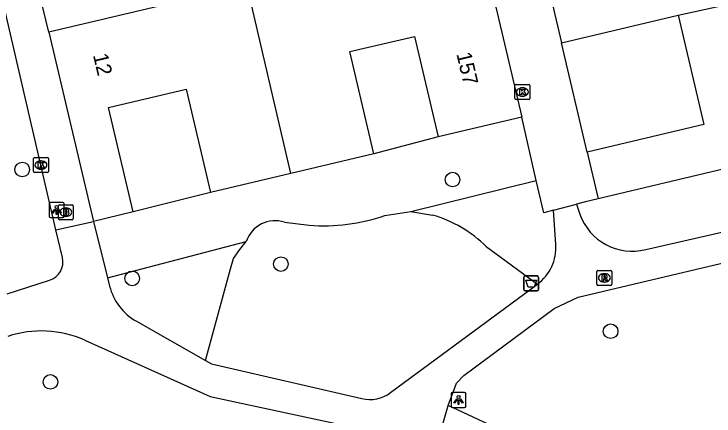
# Model space of a CAD drawing. Extents: x 162990 to 165007, y 383433 to 384336.
# Drawn here: x 164065.4 to 164112.18, y 383958.55 to 383985.38 of the extents above; entities that cross this region are included whole.
import ezdxf

# ---------------------------------------------------------------- set-up
doc = ezdxf.new("R2010")
doc.units = 0
for name, color, linetype in [('IMGEO_Afvalbak', 7, 'Continuous'), ('IMGEO_Boom', 7, 'Continuous'), ('IMGEO_Brandkraan', 7, 'Continuous'), ('IMGEO_Groenvoorziening', 7, 'Continuous'), ('IMGEO_Kolk', 7, 'Continuous'), ('IMGEO_Lichtpunt', 7, 'Continuous'), ('IMGEO_Pand', 7, 'Continuous'), ('IMGEO_Pand_nummerreeks', 7, 'Continuous'), ('IMGEO_Rioolput', 7, 'Continuous'), ('IMGEO_Voetpad_halfverhard', 7, 'Continuous'), ('IMGEO_Voetpad_open', 7, 'Continuous')]:
    doc.layers.add(name, color=color, linetype=linetype)

msp = doc.modelspace()

# ---------------------------------------------------------------- linework, layer by layer
at = {"layer": 'IMGEO_Afvalbak'}
for p, q in [((164099.571, 383967.895), (164100.361, 383967.895)), ((164100.361, 383967.895), (164099.571, 383967.895)), ((164099.471, 383966.995), (164099.471, 383967.795)), ((164099.471, 383967.795), (164099.471, 383966.995)), ((164100.461, 383967.795), (164100.461, 383966.995)), ((164100.461, 383966.995), (164100.461, 383967.795)), ((164100.361, 383966.895), (164099.571, 383966.895)), ((164099.571, 383966.895), (164100.361, 383966.895))]:
    msp.add_line(p, q, dxfattribs=at)
msp.add_lwpolyline([(164099.614, 383967.609), (164100.318, 383967.609), (164100.169, 383967.139), (164099.763, 383967.139), (164099.614, 383967.609)], dxfattribs=at)
for centre, start, end in [((164099.571, 383967.795), 90, 180), ((164099.571, 383967.795), 90, 180), ((164100.361, 383967.795), 0, 90), ((164100.361, 383967.795), 360, 90), ((164099.571, 383966.995), 180, 270), ((164099.571, 383966.995), 180, 270), ((164100.361, 383966.995), 270, 0), ((164100.361, 383966.995), 270, 0)]:
    msp.add_arc(centre, 0.1, start, end, dxfattribs=at)
at = {"layer": 'IMGEO_Boom'}
for centre in [(164065.947, 383975), (164094.708, 383974.328), (164083.237, 383968.686), (164073.296, 383967.732), (164105.273, 383964.207), (164067.835, 383960.826)]:
    msp.add_circle(centre, 0.489, dxfattribs=at)
at = {"layer": 'IMGEO_Brandkraan'}
for p, q in [((164068.361, 383971.725), (164068.361, 383972.577)), ((164068.436, 383972.651), (164069.288, 383972.651)), ((164069.362, 383972.577), (164069.362, 383971.725)), ((164068.849, 383972.431), (164068.874, 383972.431)), ((164069.288, 383971.651), (164068.436, 383971.651)), ((164068.872, 383971.871), (164068.847, 383971.871))]:
    msp.add_line(p, q, dxfattribs=at)
for points in [[(164068.361, 383971.725), (164068.361, 383972.577)], [(164068.436, 383972.651), (164069.288, 383972.651)], [(164069.362, 383972.577), (164069.362, 383971.725)], [(164068.709, 383972.351), (164068.709, 383971.951), (164068.922, 383971.951)], [(164068.94, 383972.351), (164068.709, 383972.351)], [(164068.888, 383972.27), (164068.834, 383972.27), (164068.834, 383972.194)], [(164068.834, 383972.194), (164068.887, 383972.194)], [(164068.896, 383972.118), (164068.834, 383972.118), (164068.834, 383972.037)], [(164069.288, 383971.651), (164068.436, 383971.651)], [(164068.834, 383972.037), (164068.896, 383972.037)]]:
    msp.add_lwpolyline(points, dxfattribs=at)
for centre, radius, start, end in [((164068.438, 383972.575), 0.0765, 91.552, 178.448), ((164068.438, 383972.575), 0.0765, 91.552, 178.448), ((164069.286, 383972.575), 0.0765, 1.552, 88.448), ((164069.286, 383972.575), 0.0765, 1.552, 88.448), ((164068.889, 383972.232), 0.0379, 267.8285, 90.9355), ((164068.897, 383972.077), 0.0404, 269.8759, 90.5077), ((164068.944, 383972.206), 0.145, 59.4692, 91.5367), ((164068.969, 383972.253), 0.0922, 285.5137, 58.1501), ((164068.974, 383972.061), 0.105, 301.3115, 78.989), ((164068.438, 383971.727), 0.0765, 181.552, 268.448), ((164068.438, 383971.727), 0.0765, 181.552, 268.448), ((164068.928, 383972.202), 0.251, 268.6676, 293.5347), ((164069.286, 383971.727), 0.0765, 271.552, 358.448), ((164069.286, 383971.727), 0.0765, 271.552, 358.448)]:
    msp.add_arc(centre, radius, start, end, dxfattribs=at)
for centre, major_axis, ratio, start_param, end_param in [((164068.848, 383972.151), (-0.387, 0.002), 0.722429, 4.712389, 7.853982), ((164068.873, 383972.151), (-0.39, 0.002), 0.717154, 1.570796, 4.712389)]:
    msp.add_ellipse(centre, major_axis=major_axis, ratio=ratio, start_param=start_param, end_param=end_param, dxfattribs=at)
at = {"layer": 'IMGEO_Groenvoorziening'}
for points in [[(164093.738, 383977.172), (164089.454, 383976.051)], [(164091.918, 383972.201), (164100.303, 383974.268)], [(164078.53, 383973.473), (164073.354, 383972.164)], [(164090.173, 383971.92), (164091.918, 383972.201)], [(164091.918, 383972.201), (164093.376, 383971.951)], [(164083.486, 383971.482), (164085.132, 383971.274)], [(164071.651, 383967.76), (164080.918, 383970.191)], [(164078.192, 383962.253), (164079.862, 383968.373), (164080.075, 383969.069), (164080.492, 383969.666), (164080.918, 383970.191)], [(164096.965, 383969.857), (164100.386, 383967.354)], [(164124.472, 383958.604), (164114.758, 383957.879), (164107.853, 383957.563), (164102.633, 383956.731), (164101.117, 383956.676), (164100.331, 383956.769), (164098.81, 383957.196), (164094.409, 383959.248)]]:
    msp.add_lwpolyline(points, dxfattribs=at)
for centre, radius, start, end in [((164082.856, 383969.536), 2.046, 72.0612, 161.3185), ((164086.081, 383983.861), 12.623, 265.6888, 288.9164), ((164091.028, 383963.804), 8.478, 45.5534, 73.9238)]:
    msp.add_arc(centre, radius, start, end, dxfattribs=at)
at = {"layer": 'IMGEO_Kolk'}
for p, q in [((164098.876, 383979.746), (164098.876, 383980.598)), ((164098.951, 383980.672), (164099.803, 383980.672)), ((164099.877, 383980.598), (164099.877, 383979.746)), ((164099.364, 383980.452), (164099.389, 383980.452)), ((164099.803, 383979.672), (164098.951, 383979.672)), ((164099.387, 383979.892), (164099.362, 383979.892)), ((164066.77, 383975.797), (164067.622, 383975.797)), ((164066.695, 383974.871), (164066.695, 383975.723)), ((164067.183, 383975.577), (164067.208, 383975.577)), ((164067.696, 383975.723), (164067.696, 383974.871)), ((164067.206, 383975.017), (164067.181, 383975.017)), ((164067.622, 383974.797), (164066.77, 383974.797))]:
    msp.add_line(p, q, dxfattribs=at)
for points in [[(164098.876, 383979.746), (164098.876, 383980.598)], [(164098.951, 383980.672), (164099.803, 383980.672)], [(164099.877, 383980.598), (164099.877, 383979.746)], [(164099.197, 383980.372), (164099.32, 383980.372), (164099.32, 383980.221), (164099.45, 383980.372), (164099.614, 383980.372), (164099.468, 383980.221), (164099.621, 383979.972), (164099.469, 383979.972), (164099.384, 383980.136), (164099.32, 383980.069), (164099.32, 383979.972), (164099.197, 383979.972), (164099.197, 383980.372)], [(164099.803, 383979.672), (164098.951, 383979.672)], [(164066.77, 383975.797), (164067.622, 383975.797)], [(164066.695, 383974.871), (164066.695, 383975.723)], [(164067.016, 383975.497), (164067.139, 383975.497), (164067.139, 383975.346), (164067.269, 383975.497), (164067.433, 383975.497), (164067.287, 383975.346), (164067.44, 383975.097), (164067.288, 383975.097), (164067.203, 383975.261), (164067.139, 383975.194), (164067.139, 383975.097), (164067.016, 383975.097), (164067.016, 383975.497)], [(164067.696, 383975.723), (164067.696, 383974.871)], [(164067.622, 383974.797), (164066.77, 383974.797)]]:
    msp.add_lwpolyline(points, dxfattribs=at)
for centre, start, end in [((164098.953, 383980.596), 91.552, 178.448), ((164098.953, 383980.596), 91.552, 178.448), ((164099.801, 383980.596), 1.552, 88.448), ((164099.801, 383980.596), 1.552, 88.448), ((164098.953, 383979.748), 181.552, 268.448), ((164098.953, 383979.748), 181.552, 268.448), ((164099.801, 383979.748), 271.552, 358.448), ((164099.801, 383979.748), 271.552, 358.448), ((164066.772, 383975.721), 91.552, 178.448), ((164066.772, 383975.721), 91.552, 178.448), ((164067.62, 383975.721), 1.552, 88.448), ((164067.62, 383975.721), 1.552, 88.448), ((164066.772, 383974.873), 181.552, 268.448), ((164066.772, 383974.873), 181.552, 268.448), ((164067.62, 383974.873), 271.552, 358.448), ((164067.62, 383974.873), 271.552, 358.448)]:
    msp.add_arc(centre, 0.0765, start, end, dxfattribs=at)
for centre, major_axis, ratio, start_param, end_param in [((164099.363, 383980.172), (-0.387, 0.002), 0.722429, 4.712389, 7.853982), ((164099.388, 383980.172), (-0.39, 0.002), 0.717154, 1.570796, 4.712389), ((164067.182, 383975.297), (-0.387, 0.002), 0.722429, 4.712389, 7.853982), ((164067.207, 383975.297), (-0.39, 0.002), 0.717154, 1.570796, 4.712389)]:
    msp.add_ellipse(centre, major_axis=major_axis, ratio=ratio, start_param=start_param, end_param=end_param, dxfattribs=at)
at = {"layer": 'IMGEO_Lichtpunt'}
for p, q in [((164067.75, 383972.698), (164067.75, 383971.891)), ((164067.75, 383972.698), (164067.75, 383971.891)), ((164068.652, 383972.793), (164067.844, 383972.793)), ((164068.652, 383972.793), (164067.844, 383972.793)), ((164068.746, 383971.891), (164068.746, 383972.698)), ((164068.746, 383971.891), (164068.746, 383972.698)), ((164067.844, 383971.797), (164068.652, 383971.797)), ((164067.844, 383971.797), (164068.652, 383971.797)), ((164094.61, 383960.02), (164094.61, 383959.213)), ((164094.61, 383960.02), (164094.61, 383959.213)), ((164095.512, 383960.115), (164094.704, 383960.115)), ((164095.512, 383960.115), (164094.704, 383960.115)), ((164095.606, 383959.213), (164095.606, 383960.02)), ((164095.606, 383959.213), (164095.606, 383960.02)), ((164094.704, 383959.119), (164095.512, 383959.119)), ((164094.704, 383959.119), (164095.512, 383959.119))]:
    msp.add_line(p, q, dxfattribs=at)
for points in [[(164068.124, 383972.362), (164068.163, 383972.334), (164067.975, 383972.072), (164067.937, 383972.099), (164068.124, 383972.362)], [(164068.226, 383972.314), (164068.273, 383972.314), (164068.273, 383971.992), (164068.226, 383971.992), (164068.226, 383972.314)], [(164068.336, 383972.334), (164068.374, 383972.361), (164068.561, 383972.099), (164068.522, 383972.071), (164068.336, 383972.334)], [(164094.984, 383959.684), (164095.023, 383959.656), (164094.835, 383959.394), (164094.797, 383959.421), (164094.984, 383959.684)], [(164095.086, 383959.636), (164095.133, 383959.636), (164095.133, 383959.314), (164095.086, 383959.314), (164095.086, 383959.636)], [(164095.196, 383959.656), (164095.234, 383959.683), (164095.421, 383959.421), (164095.382, 383959.393), (164095.196, 383959.656)]]:
    msp.add_lwpolyline(points, dxfattribs=at)
for centre in [(164068.249, 383972.496), (164095.109, 383959.818)]:
    msp.add_circle(centre, 0.0994, dxfattribs=at)
for centre, start, end in [((164067.844, 383972.698), 90, 180), ((164067.844, 383972.698), 90, 180), ((164068.652, 383972.698), 0, 90), ((164068.652, 383972.698), 0, 90), ((164067.844, 383971.891), 180, 270), ((164067.844, 383971.891), 180, 270), ((164068.652, 383971.891), 270, 0), ((164068.652, 383971.891), 270, 360), ((164094.704, 383960.02), 90, 180), ((164094.704, 383960.02), 90, 180), ((164095.512, 383960.02), 0, 90), ((164095.512, 383960.02), 0, 90), ((164094.704, 383959.213), 180, 270), ((164094.704, 383959.213), 180, 270), ((164095.512, 383959.213), 270, 0), ((164095.512, 383959.213), 270, 360)]:
    msp.add_arc(centre, 0.0946, start, end, dxfattribs=at)
at = {"layer": 'IMGEO_Pand'}
for points in [[(164083.905, 383974.741), (164080.991, 383987.268)], [(164097.507, 383986.21), (164099.327, 383978.491)], [(164101.282, 383986.493), (164101.999, 383983.454)], [(164109.789, 383985.292), (164114.799, 383986.411)], [(164075.475, 383985.991), (164067.723, 383984.162)], [(164101.999, 383983.454), (164109.789, 383985.292)], [(164109.789, 383985.292), (164111.512, 383977.994), (164103.699, 383976.15)], [(164067.723, 383984.162), (164070.701, 383971.538)], [(164089.454, 383976.051), (164087.845, 383982.87), (164092.154, 383983.886), (164093.738, 383977.172)], [(164073.354, 383972.164), (164071.709, 383979.134), (164076.906, 383980.36), (164078.53, 383973.473)], [(164099.327, 383978.491), (164093.738, 383977.172)], [(164089.454, 383976.051), (164083.905, 383974.741)], [(164103.699, 383976.15), (164104.431, 383973.05)], [(164112.873, 383975.042), (164104.431, 383973.05)], [(164083.905, 383974.741), (164078.53, 383973.473)], [(164073.354, 383972.164), (164070.701, 383971.538)]]:
    msp.add_lwpolyline(points, dxfattribs=at)
at = {"layer": 'IMGEO_Rioolput'}
for p, q in [((164104.352, 383967.341), (164104.352, 383968.193)), ((164104.427, 383968.267), (164105.279, 383968.267)), ((164104.84, 383968.047), (164104.865, 383968.047)), ((164105.353, 383968.193), (164105.353, 383967.341)), ((164104.863, 383967.487), (164104.838, 383967.487)), ((164105.279, 383967.267), (164104.427, 383967.267))]:
    msp.add_line(p, q, dxfattribs=at)
for points in [[(164104.352, 383967.341), (164104.352, 383968.193)], [(164104.427, 383968.267), (164105.279, 383968.267)], [(164104.941, 383967.965), (164104.689, 383967.967), (164104.689, 383967.567)], [(164104.867, 383967.886), (164104.813, 383967.886), (164104.813, 383967.805)], [(164105.353, 383968.193), (164105.353, 383967.341)], [(164104.689, 383967.567), (164104.813, 383967.567), (164104.813, 383967.729), (164104.824, 383967.729)], [(164104.813, 383967.805), (164104.865, 383967.805)], [(164104.871, 383967.7), (164104.942, 383967.567), (164105.082, 383967.567), (164105.017, 383967.693)], [(164105.279, 383967.267), (164104.427, 383967.267)]]:
    msp.add_lwpolyline(points, dxfattribs=at)
for centre, radius, start, end in [((164104.429, 383968.191), 0.0765, 91.552, 178.448), ((164104.429, 383968.191), 0.0765, 91.552, 178.448), ((164104.873, 383967.79), 0.0964, 77.0061, 93.1865), ((164104.887, 383967.847), 0.0378, 276.6634, 79.6772), ((164104.94, 383967.855), 0.109, 350.3612, 89.416), ((164104.938, 383967.855), 0.112, 277.5842, 350.9817), ((164105.277, 383968.191), 0.0765, 1.552, 88.448), ((164105.277, 383968.191), 0.0765, 1.552, 88.448), ((164104.823, 383967.676), 0.0533, 26.0293, 88.6989), ((164104.849, 383967.994), 0.19, 274.7715, 282.9687), ((164104.922, 383967.64), 0.108, 29.5134, 73.7905), ((164104.429, 383967.343), 0.0765, 181.552, 268.448), ((164104.429, 383967.343), 0.0765, 181.552, 268.448), ((164105.277, 383967.343), 0.0765, 271.552, 358.448), ((164105.277, 383967.343), 0.0765, 271.552, 358.448)]:
    msp.add_arc(centre, radius, start, end, dxfattribs=at)
for centre, major_axis, ratio, start_param, end_param in [((164104.839, 383967.767), (-0.387, 0.002), 0.722429, 4.712389, 7.853982), ((164104.864, 383967.767), (-0.39, 0.002), 0.717154, 1.570796, 4.712389)]:
    msp.add_ellipse(centre, major_axis=major_axis, ratio=ratio, start_param=start_param, end_param=end_param, dxfattribs=at)
at = {"layer": 'IMGEO_Voetpad_halfverhard'}
for points in [[(164103.001, 383972.686), (164103.21, 383972.024)], [(164101.604, 383969.99), (164101.446, 383972.286)], [(164070.701, 383971.538), (164071.651, 383967.76)], [(164068.631, 383969.134), (164068.201, 383970.978)], [(164107.618, 383969.659), (164113.781, 383971.067)], [(164094.409, 383959.248), (164094.962, 383960.741), (164095.46, 383961.254), (164101.5, 383965.727), (164103.103, 383966.472), (164118.83, 383970.195), (164119.488, 383970.242), (164120.127, 383970.08), (164124.527, 383968.171), (164127.006, 383967.096)], [(164064.931, 383966.695), (164067.766, 383967.602)], [(164071.651, 383967.76), (164071.789, 383967.21)], [(164090.565, 383960.105), (164100.386, 383967.354)], [(164073.576, 383964.871), (164078.192, 383962.253)], [(164070.124, 383963.605), (164078.511, 383959.84), (164088.163, 383957.785)], [(164078.192, 383962.253), (164078.587, 383962.029), (164088.638, 383959.709)], [(164093.763, 383952.722), (164093.505, 383955.612), (164093.579, 383956.38), (164094.409, 383959.248)]]:
    msp.add_lwpolyline(points, dxfattribs=at)
for centre, radius, start, end in [((164106.714, 383973.264), 3.716, 199.4858, 284.0849), ((164098.594, 383969.782), 3.017, 306.4386, 3.9615), ((164067.369, 383968.837), 1.297, 287.8456, 13.2544), ((164075.415, 383968.128), 3.74, 194.2092, 240.5505), ((164067.229, 383957.105), 7.116, 65.9949, 108.417), ((164089.173, 383961.991), 2.344, 256.7959, 306.4294)]:
    msp.add_arc(centre, radius, start, end, dxfattribs=at)
at = {"layer": 'IMGEO_Voetpad_open'}
for points in [[(164068.201, 383970.978), (164062.33, 383996.156)], [(164067.723, 383984.162), (164066.393, 383989.692)], [(164103.699, 383976.15), (164101.999, 383983.454)], [(164100.303, 383974.268), (164099.327, 383978.491)], [(164101.446, 383972.286), (164100.805, 383972.097), (164100.303, 383974.268)], [(164104.431, 383973.05), (164103.595, 383972.839), (164103.001, 383972.686)], [(164101.446, 383972.286), (164103.001, 383972.686)], [(164068.201, 383970.978), (164070.701, 383971.538)]]:
    msp.add_lwpolyline(points, dxfattribs=at)

# ---------------------------------------------------------------- texts
at = {"layer": 'IMGEO_Pand_nummerreeks'}
for s, rotation, p in [('12', 283.2734, (164070.673, 383982.633)), ('157', 283.267, (164094.96, 383982.715))]:
    msp.add_text(s, height=1, rotation=rotation, dxfattribs=at).set_placement(p)

doc.saveas('drawing.dxf')
